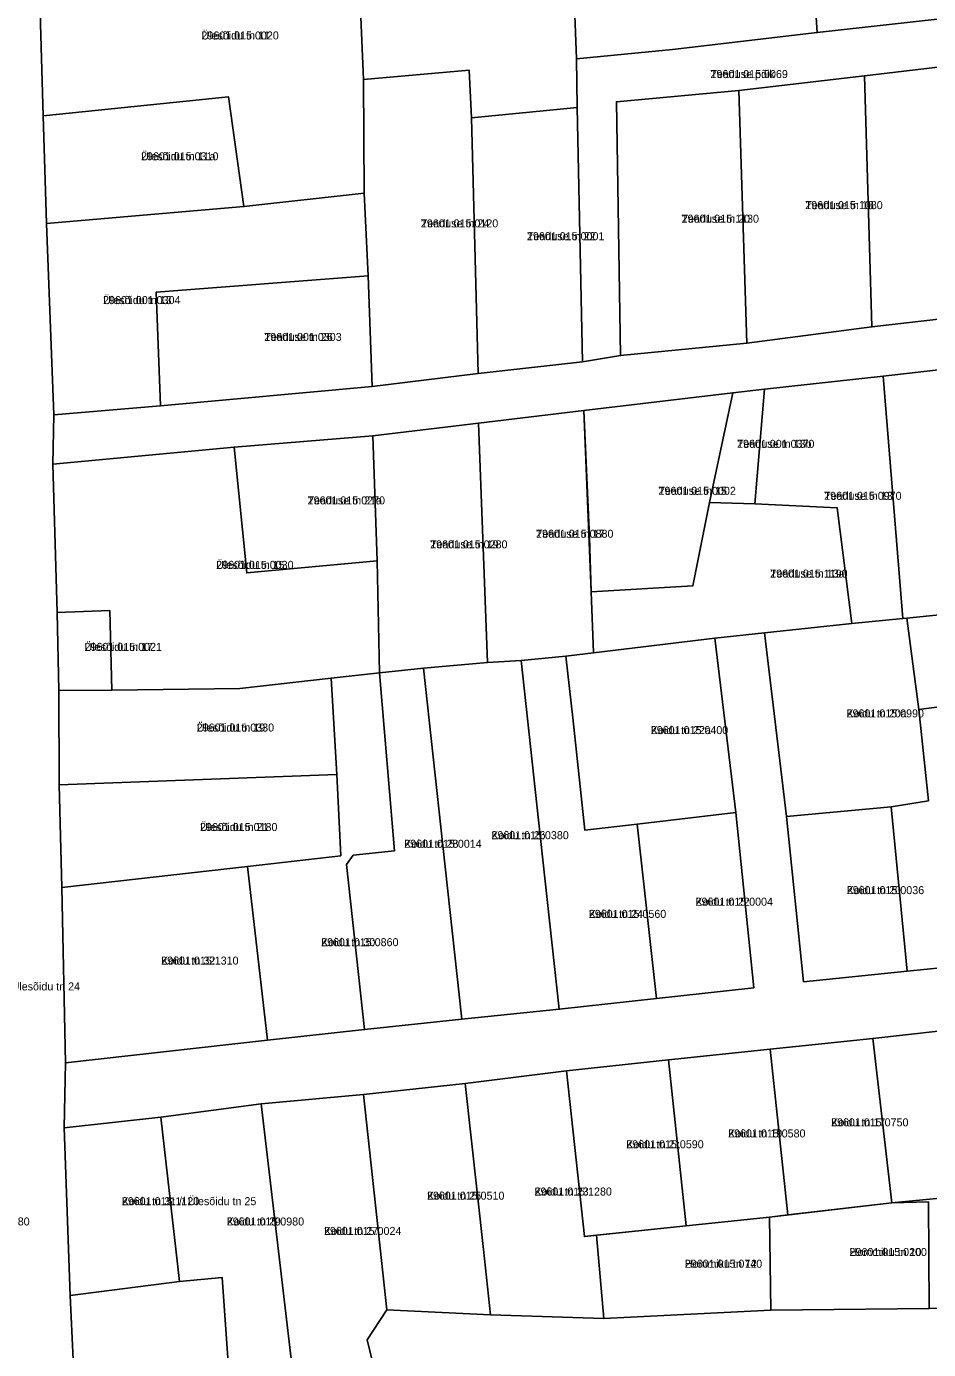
# Model space of a CAD drawing. Extents: x 518839 to 525192, y 6573164 to 6576561.
# Drawn here: x 524240.2 to 524409.2, y 6573866.6 to 6574114.7 of the extents above; entities that cross this region are included whole.
import ezdxf

# ---------------------------------------------------------------- set-up
doc = ezdxf.new("R2010")
doc.units = 0
for name, color, linetype in [('L_AADRESS', 7, 'Continuous'), ('PIIR', 7, 'Continuous'), ('TUNNUS', 7, 'Continuous')]:
    doc.layers.add(name, color=color, linetype=linetype)

msp = doc.modelspace()

# ---------------------------------------------------------------- linework, layer by layer
at = {"layer": 'PIIR'}
for points in [[(524238.98, 6574261.37), (524240.23, 6574215.18), (524240.48, 6574210.62), (524241.02, 6574197.83), (524240.91, 6574193.14), (524240.65, 6574181.86), (524242.13, 6574138.99), (524243.35, 6574097.92), (524243.96, 6574077.71), (524245.35, 6574041.84), (524245.17, 6574032.64), (524245.98, 6574004.81), (524246.26, 6573990.17), (524246.35, 6573972.48), (524246.84, 6573953.26), (524247.54, 6573920.4), (524247.28, 6573908.17), (524248.4, 6573876.78), (524250.25, 6573836.78)], [(524494.16, 6574128.57), (524494.48, 6574108.1), (524495.1, 6574069.37), (524487.94, 6574068.74), (524487.43, 6574095.74), (524487.07, 6574112.5), (524484.49, 6574114.46), (524462.76, 6574112.31), (524442.26, 6574110.41), (524420.48, 6574108.17), (524397.24, 6574105.44), (524373.66, 6574102.67), (524350.74, 6574100.56), (524351.53, 6574052.97), (524344.36, 6574051.79), (524343.39, 6574099.47), (524343.25, 6574108.62), (524361.28, 6574110.35), (524388.38, 6574113.52), (524412.54, 6574116.25)], [(524422.49, 6574051.59), (524400.72, 6574049.09), (524378.46, 6574046.7), (524372.58, 6574046.01), (524344.66, 6574042.65), (524324.93, 6574040.28), (524305.09, 6574037.93), (524279.14, 6574035.8), (524245.17, 6574032.64), (524245.35, 6574041.84), (524265.3, 6574043.52), (524305, 6574047.2), (524324.84, 6574049.63), (524344.36, 6574051.79), (524351.53, 6574052.97), (524375.15, 6574055.28), (524398.61, 6574058.33), (524421.96, 6574061.02)], [(524417.7, 6573927.05), (524398.81, 6573924.96), (524379.56, 6573922.97), (524360.48, 6573920.93), (524341.39, 6573918.9), (524322.43, 6573916.51), (524303.34, 6573914.44), (524284.19, 6573912.71), (524265.4, 6573910.2), (524247.28, 6573908.17), (524247.54, 6573920.4), (524285.34, 6573924.64), (524303.57, 6573926.62), (524321.79, 6573928.59), (524340.02, 6573930.44), (524358.25, 6573932.44), (524376.48, 6573934.43), (524373.1, 6573967.34), (524369.18, 6574000.02), (524378.5, 6574001.01), (524382.6, 6573966.55), (524385.81, 6573935.57), (524405.2, 6573937.58), (524425.08, 6573939.54)]]:
    msp.add_lwpolyline(points, dxfattribs=at)
for points in [[(524242.13, 6574138.99), (524287.15, 6574143.56), (524287.66, 6574127.29), (524302.37, 6574128.15), (524303.36, 6574104.74), (524303.45, 6574083.4), (524280.95, 6574080.9), (524278.06, 6574101.45), (524243.35, 6574097.92)], [(524386.78, 6574137.5), (524396.86, 6574138.64), (524412.39, 6574140.52), (524412.54, 6574116.25), (524388.38, 6574113.52)], [(524343.25, 6574108.62), (524342.34, 6574133.11), (524351.74, 6574133.81), (524376.8, 6574136.64), (524386.78, 6574137.5), (524388.38, 6574113.52), (524361.28, 6574110.35)], [(524323.13, 6574106.49), (524303.36, 6574104.74), (524302.37, 6574128.15), (524312.35, 6574129.57), (524332.01, 6574131.89), (524342.34, 6574133.11), (524343.25, 6574108.62), (524343.39, 6574099.47), (524323.61, 6574097.54)], [(524420.48, 6574108.17), (524421.96, 6574061.02), (524398.61, 6574058.33), (524397.24, 6574105.44)], [(524304.22, 6574067.89), (524303.45, 6574083.4), (524303.36, 6574104.74), (524323.13, 6574106.49), (524323.61, 6574097.54), (524324.84, 6574049.63), (524305, 6574047.2)], [(524373.66, 6574102.67), (524397.24, 6574105.44), (524398.61, 6574058.33), (524375.15, 6574055.28)], [(524350.74, 6574100.56), (524373.66, 6574102.67), (524375.15, 6574055.28), (524351.53, 6574052.97)], [(524243.35, 6574097.92), (524278.06, 6574101.45), (524280.95, 6574080.9), (524243.96, 6574077.71)], [(524323.61, 6574097.54), (524343.39, 6574099.47), (524344.36, 6574051.79), (524324.84, 6574049.63)], [(524264.49, 6574064.83), (524265.3, 6574043.52), (524245.35, 6574041.84), (524243.96, 6574077.71), (524280.95, 6574080.9), (524303.45, 6574083.4), (524304.22, 6574067.89)], [(524304.22, 6574067.89), (524305, 6574047.2), (524265.3, 6574043.52), (524264.49, 6574064.83)], [(524404.39, 6574003.69), (524400.72, 6574049.09), (524422.49, 6574051.59), (524424.01, 6574005.71), (524405.13, 6574003.76)], [(524378.46, 6574046.7), (524400.72, 6574049.09), (524404.39, 6574003.69), (524394.82, 6574002.77), (524392.13, 6574024.43), (524376.69, 6574025.16)], [(524344.66, 6574042.65), (524372.58, 6574046.01), (524368.21, 6574025.43), (524365.03, 6574009.78), (524346.02, 6574008.66)], [(524378.46, 6574046.7), (524376.69, 6574025.16), (524368.21, 6574025.43), (524372.58, 6574046.01)], [(524344.66, 6574042.65), (524345.67, 6574018.95), (524346.02, 6574008.66), (524346.43, 6573997.26), (524341.27, 6573996.64), (524332.91, 6573995.79), (524326.57, 6573995.43), (524324.93, 6574040.28)], [(524306.33, 6573993.51), (524305.92, 6574014.52), (524305.09, 6574037.93), (524324.93, 6574040.28), (524326.57, 6573995.43), (524314.6, 6573994.34)], [(524279.14, 6574035.8), (524305.09, 6574037.93), (524305.92, 6574014.52), (524281.49, 6574012.22)], [(524245.98, 6574004.81), (524245.17, 6574032.64), (524279.14, 6574035.8), (524281.49, 6574012.22), (524305.92, 6574014.52), (524306.33, 6573993.51), (524297.31, 6573992.49), (524280.18, 6573990.55), (524256.2, 6573990.27), (524255.81, 6574005.16)], [(524346.43, 6573997.26), (524346.02, 6574008.66), (524365.03, 6574009.78), (524368.21, 6574025.43), (524376.69, 6574025.16), (524392.13, 6574024.43), (524394.82, 6574002.77), (524378.5, 6574001.01), (524369.18, 6574000.02)], [(524405.13, 6574003.76), (524424.01, 6574005.71), (524444.64, 6574008.11), (524466.54, 6574010.65), (524488.47, 6574012.71), (524493.76, 6574013.6), (524495.03, 6574002.32), (524468.55, 6573999.21), (524471.22, 6573976.51), (524459.04, 6573975.23), (524439.93, 6573973.23), (524439.55, 6573975.52), (524421.88, 6573973.78), (524421.27, 6573988.42), (524407.39, 6573986.59)], [(524255.81, 6574005.16), (524256.2, 6573990.27), (524246.26, 6573990.17), (524245.98, 6574004.81)], [(524378.5, 6574001.01), (524394.82, 6574002.77), (524404.39, 6574003.69), (524405.13, 6574003.76), (524407.39, 6573986.59), (524409.21, 6573969.52), (524402.23, 6573968.39), (524382.6, 6573966.55)], [(524344.85, 6573963.98), (524342.6, 6573985.05), (524341.27, 6573996.64), (524346.43, 6573997.26), (524369.18, 6574000.02), (524373.1, 6573967.34), (524354.66, 6573965.15)], [(524321.79, 6573928.59), (524318.23, 6573961.14), (524314.6, 6573994.34), (524326.57, 6573995.43), (524332.91, 6573995.79), (524336.48, 6573962.98), (524340.02, 6573930.44)], [(524340.02, 6573930.44), (524336.48, 6573962.98), (524332.91, 6573995.79), (524341.27, 6573996.64), (524342.6, 6573985.05), (524344.85, 6573963.98), (524354.66, 6573965.15), (524358.25, 6573932.44)], [(524281.63, 6573957.21), (524299.09, 6573959.19), (524298.37, 6573974.42), (524297.31, 6573992.49), (524306.33, 6573993.51), (524309.19, 6573960.15), (524301.44, 6573959.3), (524300.19, 6573957.54), (524303.57, 6573926.62), (524285.34, 6573924.64)], [(524303.57, 6573926.62), (524300.19, 6573957.54), (524301.44, 6573959.3), (524309.19, 6573960.15), (524306.33, 6573993.51), (524314.6, 6573994.34), (524318.23, 6573961.14), (524321.79, 6573928.59)], [(524246.26, 6573990.17), (524256.2, 6573990.27), (524280.18, 6573990.55), (524297.31, 6573992.49), (524298.37, 6573974.42), (524246.35, 6573972.48)], [(524402.23, 6573968.39), (524409.21, 6573969.52), (524407.39, 6573986.59), (524421.27, 6573988.42), (524421.88, 6573973.78), (524421.96, 6573970.52), (524425.08, 6573939.54), (524405.2, 6573937.58)], [(524246.35, 6573972.48), (524298.37, 6573974.42), (524299.09, 6573959.19), (524281.63, 6573957.21), (524246.84, 6573953.26)], [(524405.2, 6573937.58), (524385.81, 6573935.57), (524382.6, 6573966.55), (524402.23, 6573968.39)], [(524358.25, 6573932.44), (524354.66, 6573965.15), (524373.1, 6573967.34), (524376.48, 6573934.43)], [(524281.63, 6573957.21), (524285.34, 6573924.64), (524247.54, 6573920.4), (524246.84, 6573953.26)], [(524417.7, 6573927.05), (524421.11, 6573895.96), (524402.36, 6573894.13), (524398.81, 6573924.96)], [(524379.56, 6573922.97), (524398.81, 6573924.96), (524402.36, 6573894.13), (524382.87, 6573891.87)], [(524360.48, 6573920.93), (524363.79, 6573889.84), (524344.73, 6573887.81), (524341.39, 6573918.9)], [(524360.48, 6573920.93), (524379.56, 6573922.97), (524382.87, 6573891.87), (524379.45, 6573891.48), (524363.79, 6573889.84)], [(524341.39, 6573918.9), (524344.73, 6573887.81), (524347.01, 6573888.05), (524348.36, 6573872.46), (524327.15, 6573873.14), (524325.81, 6573885.42), (524322.43, 6573916.51)], [(524325.81, 6573885.42), (524327.15, 6573873.14), (524307.7, 6573874.1), (524306.7, 6573883.35), (524303.34, 6573914.44), (524322.43, 6573916.51)], [(524303.34, 6573914.44), (524306.7, 6573883.35), (524307.7, 6573874.1), (524304.04, 6573868.46), (524305.58, 6573861.99), (524290.05, 6573862.75), (524284.19, 6573912.71)], [(524265.4, 6573910.2), (524284.19, 6573912.71), (524290.05, 6573862.75), (524278.05, 6573863.34), (524276.86, 6573880.16), (524268.86, 6573879.4)], [(524247.28, 6573908.17), (524265.4, 6573910.2), (524268.86, 6573879.4), (524248.4, 6573876.78)], [(524379.45, 6573891.48), (524383.09, 6573891.9), (524402.36, 6573894.13), (524409.23, 6573894.31), (524409.34, 6573874.31), (524379.68, 6573874.03)], [(524347.01, 6573888.05), (524363.79, 6573889.84), (524379.45, 6573891.48), (524379.68, 6573874.03), (524348.36, 6573872.46)], [(524248.4, 6573876.78), (524268.86, 6573879.4), (524276.86, 6573880.16), (524278.05, 6573863.34), (524278.36, 6573840.72), (524278.14, 6573836.9), (524250.25, 6573836.78)], [(524307.7, 6573874.1), (524327.15, 6573873.14), (524348.36, 6573872.46), (524379.68, 6573874.03), (524409.34, 6573874.31), (524439.69, 6573875.03), (524469.67, 6573875.71), (524499.86, 6573876.34), (524539.01, 6573876.82), (524547.46, 6573876.94), (524542.18, 6573861.09), (524539.64, 6573864.28), (524508.18, 6573863.78), (524486.83, 6573863.15), (524465.01, 6573862.55), (524443.99, 6573861.97), (524417.49, 6573861.68), (524390.99, 6573861.38), (524377.97, 6573864.01), (524347.85, 6573863.73), (524317.26, 6573863.72), (524305.58, 6573861.99), (524304.04, 6573868.46)]]:
    msp.add_lwpolyline(points, close=True, dxfattribs=at)

# ---------------------------------------------------------------- texts
at = {"layer": 'L_AADRESS'}
for s, p in [('Ülesõidu tn 11', (524272.98, 6574112.23)), ('Teaduse põik', (524368.36, 6574104.99)), ('Ülesõidu tn 11a', (524261.67, 6574089.58)), ('Teaduse tn 18', (524386.13, 6574080.42)), ('Teaduse tn 20', (524362.95, 6574077.88)), ('Teaduse tn 24', (524314.1, 6574077)), ('Teaduse tn 22', (524333.98, 6574074.6)), ('Ülesõidu tn 13', (524254.56, 6574062.62)), ('Teaduse tn 26', (524284.76, 6574055.71)), ('Teaduse tn 13b', (524373.34, 6574035.68)), ('Teaduse tn 15', (524358.62, 6574026.87)), ('Teaduse tn 13', (524389.67, 6574025.93)), ('Teaduse tn 21a', (524292.88, 6574025.07)), ('Teaduse tn 17', (524335.68, 6574018.82)), ('Teaduse tn 19', (524315.83, 6574016.83)), ('Ülesõidu tn 15', (524275.75, 6574012.99)), ('Teaduse tn 13a', (524379.55, 6574011.35)), ('Ülesõidu tn 17', (524251.09, 6573997.61)), ('Koidu tn 20a', (524393.86, 6573985.14)), ('Ülesõidu tn 19', (524272.1, 6573982.49)), ('Koidu tn 22a', (524357.19, 6573982.01)), ('Ülesõidu tn 21', (524272.72, 6573963.84)), ('Koidu tn 26', (524327.31, 6573962.31)), ('Koidu tn 28', (524310.99, 6573960.7)), ('Koidu tn 20', (524393.9, 6573952.01)), ('Koidu tn 22', (524365.57, 6573949.84)), ('Koidu tn 24', (524345.58, 6573947.56)), ('Koidu tn 30', (524295.41, 6573942.25)), ('Koidu tn 32', (524265.44, 6573938.8)), ('Koidu tn 36 // Ülesõidu tn 24', (524225.04, 6573933.96)), ('Koidu tn 17', (524390.96, 6573908.48)), ('Koidu tn 21', (524352.59, 6573904.37)), ('Koidu tn 19', (524371.67, 6573906.4)), ('Koidu tn 25', (524315.25, 6573894.73)), ('Koidu tn 23', (524335.39, 6573895.51)), ('Koidu tn 31 // Ülesõidu tn 25', (524258.07, 6573893.7)), ('Koidu tn 29', (524277.72, 6573889.89)), ('Koidu tn 27', (524295.95, 6573888.12)), ('Hommiku tn 12', (524363.56, 6573881.97)), ('Hommiku tn 10', (524394.42, 6573884.17))]:
    msp.add_text(s, height=1.5, dxfattribs=at).set_placement(p)
at = {"layer": 'TUNNUS'}
for s, p in [('29601:015:0020', (524272.98, 6574112.23)), ('29601:015:0069', (524368.36, 6574104.99)), ('29601:015:0310', (524261.67, 6574089.58)), ('29601:015:1080', (524386.13, 6574080.42)), ('29601:015:1130', (524362.95, 6574077.88)), ('29601:015:0120', (524314.1, 6574077)), ('29601:015:0001', (524333.98, 6574074.6)), ('29601:001:0304', (524254.56, 6574062.62)), ('29601:001:0303', (524284.76, 6574055.71)), ('29601:001:0370', (524373.34, 6574035.68)), ('29601:015:0002', (524358.62, 6574026.87)), ('29601:015:0970', (524389.67, 6574025.93)), ('29601:015:0270', (524292.88, 6574025.07)), ('29601:015:0880', (524335.68, 6574018.82)), ('29601:015:0280', (524315.83, 6574016.83)), ('29601:015:0030', (524275.75, 6574012.99)), ('29601:015:1190', (524379.55, 6574011.35)), ('29601:015:0021', (524251.09, 6573997.61)), ('29601:015:0990', (524393.86, 6573985.14)), ('29601:015:0330', (524272.1, 6573982.49)), ('29601:015:0400', (524357.19, 6573982.01)), ('29601:015:0180', (524272.72, 6573963.84)), ('29601:015:0380', (524327.31, 6573962.31)), ('29601:015:0014', (524310.99, 6573960.7)), ('29601:015:0036', (524393.9, 6573952.01)), ('29601:015:0004', (524365.57, 6573949.84)), ('29601:015:0560', (524345.58, 6573947.56)), ('29601:015:0860', (524295.41, 6573942.25)), ('29601:015:1310', (524265.44, 6573938.8)), ('29601:015:0750', (524390.96, 6573908.48)), ('29601:015:0590', (524352.59, 6573904.37)), ('29601:015:0580', (524371.67, 6573906.4)), ('29601:015:0510', (524315.25, 6573894.73)), ('29601:015:1280', (524335.39, 6573895.51)), ('29601:015:1120', (524258.07, 6573893.7)), ('29601:013:0780', (524226.3, 6573889.9)), ('29601:015:0980', (524277.72, 6573889.89)), ('29601:015:0024', (524295.95, 6573888.12)), ('29601:015:0740', (524363.56, 6573881.97)), ('29601:015:0200', (524394.42, 6573884.17))]:
    msp.add_text(s, height=1.5, dxfattribs=at).set_placement(p)

doc.saveas('drawing.dxf')
